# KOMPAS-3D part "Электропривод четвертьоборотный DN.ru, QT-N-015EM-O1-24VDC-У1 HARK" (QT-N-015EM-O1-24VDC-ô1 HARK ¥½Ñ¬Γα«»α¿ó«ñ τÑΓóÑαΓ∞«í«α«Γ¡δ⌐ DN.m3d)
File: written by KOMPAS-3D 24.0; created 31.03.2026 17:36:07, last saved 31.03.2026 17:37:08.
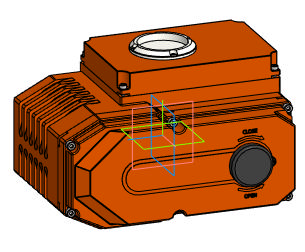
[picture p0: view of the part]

Document properties: Автор: DN.RU; Полное имя файла: D:\PROJECT CAD\DN.RU\...195\Исходники\24В\QT-N-015EM-O1-24VDC-У1 HARK Электропривод четвертьоборотный DN.ru\QT-N-015EM-O1-24VDC-У1 HARK Электропривод четвертьоборотный DN.m3d

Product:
- Body: Твердое тело1  | qty 1
    Масса: 18.642152
- Part/product: Электропривод четвертьоборотный DN.ru  | designation QT-N-015EM-O1-24VDC-У1 HARK
    Масса: 4.6
    Раздел спецификации: Прочие изделия
    Комментарий: D300-14487
    Примечание: D300-14488
    additional columns: Сталь

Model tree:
1. Твердое тело1  (labels: Твердое тело1)

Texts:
  QT-N-015EM-O1-24VDC-У1 HARK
